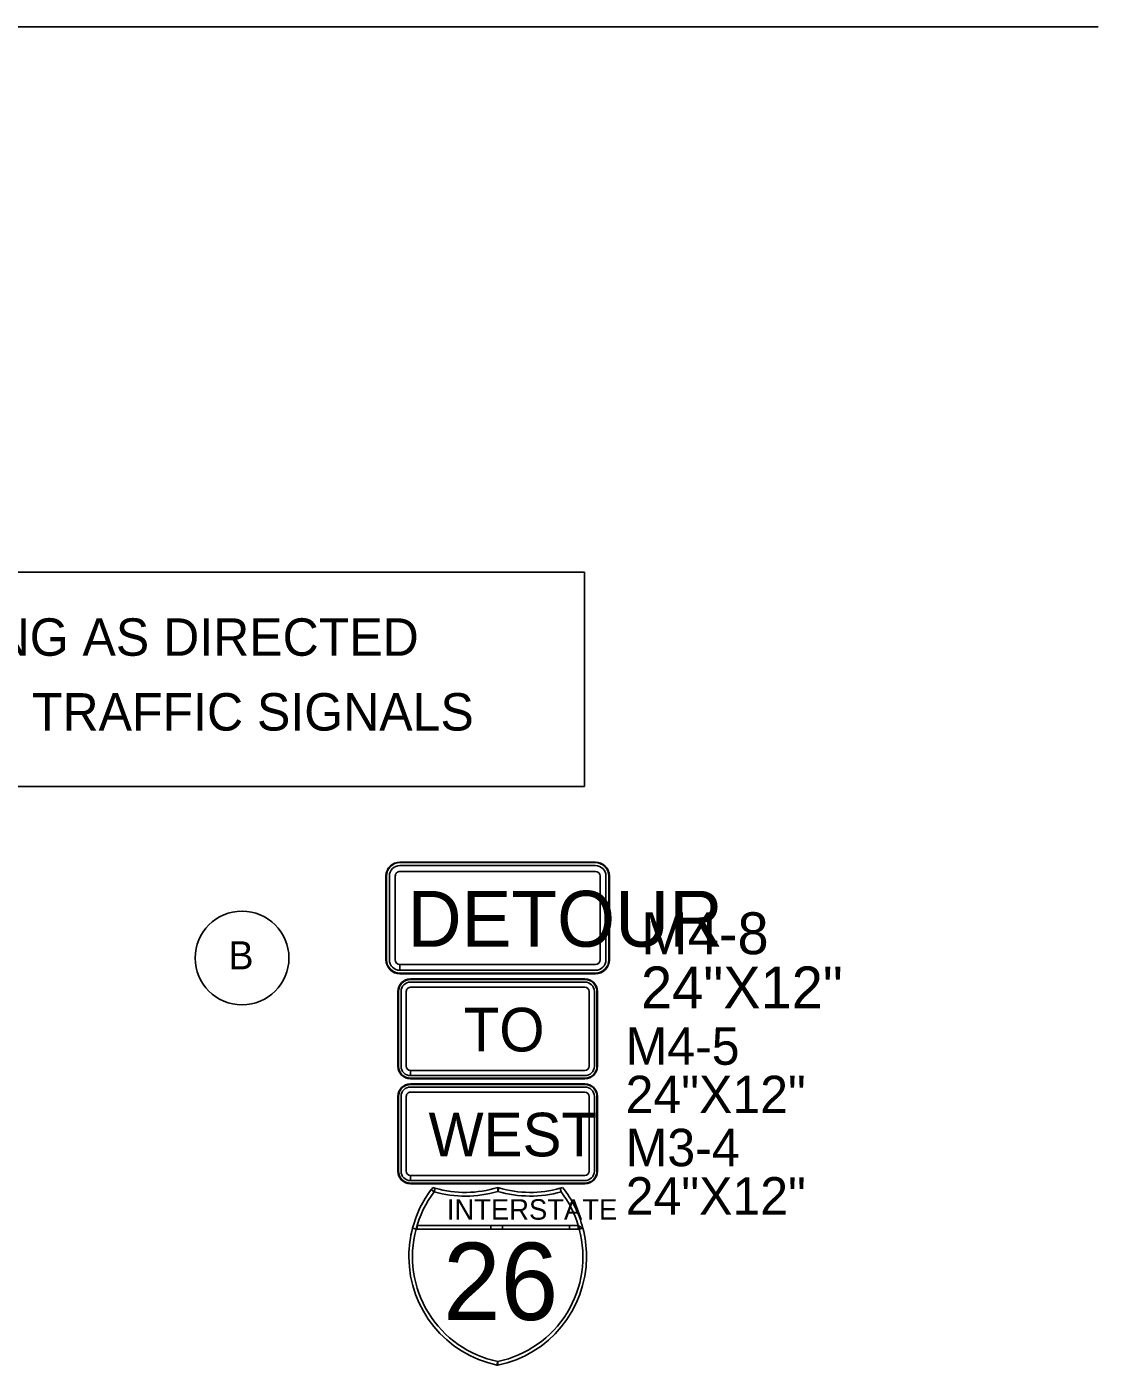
# Model space of a CAD drawing. Extents: x 886234 to 968767, y 455416 to 684046.
# Drawn here: x 935566 to 939863, y 530332 to 535699 of the extents above; entities that cross this region are included whole.
import ezdxf

# ---------------------------------------------------------------- set-up
doc = ezdxf.new("R2010")
doc.units = 0
for name, color, linetype in [('Scratch_Level_3', 7, 'Continuous'), ('TC DEV SIGN BLACK 239', 7, 'Continuous'), ('TC DEV SIGN BLACK ZERO', 7, 'Continuous'), ('TC DEV SIGN ORANGE', 7, 'Continuous'), ('TC DEV SIGN WHITE', 7, 'Continuous'), ('TC LABEL TEXT', 7, 'Continuous')]:
    doc.layers.add(name, color=color, linetype=linetype)

msp = doc.modelspace()

# ---------------------------------------------------------------- linework, layer by layer
at = {"layer": 'Scratch_Level_3'}
msp.add_line((904674.3, 535698.9), (939863.1, 535698.9), dxfattribs=at)
at = {"layer": 'TC DEV SIGN BLACK 239'}
for p, q in [((937067.2, 531409.7), (937067.2, 531109.7)), ((937088, 531409.7), (937088, 531109.7)), ((937804.8, 531447.2), (937104.7, 531447.2)), ((937804.8, 531426.4), (937104.7, 531426.4)), ((937821.4, 531109.7), (937821.4, 531409.7)), ((937842.3, 531109.7), (937842.3, 531409.7)), ((937104.7, 531072.2), (937104.7, 531093)), ((937104.9, 531093), (937804.8, 531093)), ((937104.9, 531093), (937104.9, 531072.2)), ((937104.9, 531072.2), (937804.8, 531072.2))]:
    msp.add_line(p, q, dxfattribs=at)
for centre, major_axis, start_param, end_param in [((937104.7, 531409.7), (37.5, 0), 1.570796, 3.141593), ((937104.7, 531409.7), (16.7, 0), 1.570796, 3.141593), ((937804.8, 531409.7), (37.5, 0), 0, 1.570796), ((937804.8, 531409.7), (16.7, 0), 0, 1.570796), ((937104.7, 531109.7), (37.5, 0), 3.141593, 4.712389), ((937104.7, 531109.7), (16.7, 0), 3.141593, 4.712389), ((937804.8, 531109.7), (37.5, 0), 4.712389, 6.283185), ((937804.8, 531109.7), (16.7, 0), 4.712389, 6.283185)]:
    msp.add_ellipse(centre, major_axis=major_axis, ratio=0.999865, start_param=start_param, end_param=end_param, dxfattribs=at)
at = {"layer": 'TC DEV SIGN BLACK ZERO'}
for p, q in [((937846.7, 532349.4), (937062.6, 532349.4)), ((937062.6, 532347), (937062.6, 532347.1)), ((937846.7, 532347), (937062.6, 532347.1)), ((937846.7, 532335.4), (937062.6, 532335.4)), ((937846.7, 532347), (937846.7, 532347)), ((937006.6, 532293.4), (937006.6, 531957.4)), ((937009, 532293.4), (937009, 531957.4)), ((937009, 532293.4), (937009, 532293.4)), ((937020.6, 532293.4), (937020.6, 531957.4)), ((937044, 532293.4), (937044, 531957.4)), ((937846.7, 532312), (937062.6, 532312)), ((937865.4, 531957.4), (937865.4, 532293.4)), ((937888.8, 531957.4), (937888.8, 532293.4)), ((937900.4, 532293.4), (937900.4, 532293.4)), ((937900.4, 531957.4), (937900.4, 532293.4)), ((937902.8, 531957.4), (937902.8, 532293.4)), ((937009, 531957.4), (937009, 531957.4)), ((937900.4, 531957.4), (937900.4, 531957.4)), ((937062.6, 531915.4), (937062.6, 531938.7)), ((937062.6, 531901.4), (937062.6, 531903.7)), ((937062.6, 531903.7), (937062.6, 531903.7)), ((937062.7, 531903.7), (937846.7, 531903.7)), ((937062.7, 531903.7), (937062.7, 531901.4)), ((937062.7, 531901.4), (937846.7, 531901.4)), ((937062.9, 531938.7), (937846.7, 531938.7)), ((937062.9, 531938.7), (937062.9, 531915.4)), ((937062.9, 531915.4), (937846.7, 531915.4)), ((937846.7, 531903.7), (937846.7, 531903.7)), ((937804.8, 531880.5), (937104.7, 531880.5)), ((937104.7, 531878.5), (937104.7, 531878.5)), ((937804.8, 531878.4), (937104.7, 531878.5)), ((937804.8, 531868), (937104.7, 531868)), ((937804.8, 531847.2), (937104.7, 531847.2)), ((937804.8, 531878.4), (937804.8, 531878.5)), ((937054.7, 531830.5), (937054.7, 531530.5)), ((937056.7, 531830.5), (937056.7, 531530.5)), ((937056.7, 531830.5), (937056.7, 531830.5)), ((937067.2, 531830.5), (937067.2, 531530.5)), ((937088, 531830.5), (937088, 531530.5)), ((937821.4, 531530.5), (937821.4, 531830.5)), ((937842.3, 531530.5), (937842.3, 531830.5)), ((937852.7, 531830.5), (937852.7, 531830.5)), ((937852.7, 531530.5), (937852.7, 531830.5)), ((937854.8, 531530.5), (937854.8, 531830.5)), ((937056.7, 531530.5), (937056.7, 531530.5)), ((937852.7, 531530.5), (937852.7, 531530.5)), ((937104.7, 531493), (937104.7, 531513.9)), ((937104.7, 531480.5), (937104.7, 531482.6)), ((937104.7, 531482.6), (937104.7, 531482.6)), ((937104.7, 531482.6), (937804.8, 531482.6)), ((937104.7, 531482.6), (937104.7, 531480.5)), ((937104.7, 531480.5), (937804.8, 531480.5)), ((937104.9, 531513.9), (937804.8, 531513.9)), ((937104.9, 531513.9), (937104.9, 531493)), ((937104.9, 531493), (937804.8, 531493)), ((937804.8, 531482.6), (937804.8, 531482.6)), ((937054.7, 531409.7), (937054.7, 531109.7)), ((937056.7, 531409.7), (937056.7, 531109.7)), ((937056.7, 531409.7), (937056.8, 531409.7)), ((937804.8, 531459.7), (937104.7, 531459.7)), ((937104.7, 531457.6), (937104.7, 531457.6)), ((937804.8, 531457.6), (937104.7, 531457.6)), ((937804.8, 531457.6), (937804.8, 531457.6)), ((937852.7, 531409.7), (937852.7, 531409.7)), ((937852.7, 531109.7), (937852.7, 531409.7)), ((937854.8, 531109.7), (937854.8, 531409.7)), ((937056.8, 531109.7), (937056.7, 531109.7)), ((937852.7, 531109.7), (937852.7, 531109.7)), ((937104.7, 531059.7), (937104.7, 531061.8)), ((937104.7, 531061.8), (937104.7, 531061.8)), ((937104.7, 531061.8), (937804.8, 531061.8)), ((937104.7, 531061.8), (937104.7, 531059.7)), ((937104.7, 531059.7), (937804.8, 531059.7)), ((937455.1, 531029.8), (937454.8, 531044.2)), ((937705.5, 531041.4), (937709.5, 531027.1)), ((937804.8, 531061.8), (937804.8, 531061.8)), ((937427.6, 530892.3), (937131.7, 530892.3)), ((937131.7, 530877.4), (937427.6, 530877.4)), ((937474.5, 530892.3), (937427.6, 530892.3)), ((937427.6, 530877.4), (937474.5, 530877.4)), ((937742.9, 530892.3), (937474.5, 530892.3)), ((937474.5, 530877.4), (937742.9, 530877.4)), ((937777.8, 530892.3), (937742.9, 530892.3)), ((937742.9, 530877.4), (937777.8, 530877.4)), ((937098.5, 530770.2), (937098.5, 530765.8)), ((937811, 530765.7), (937811, 530770.4))]:
    msp.add_line(p, q, dxfattribs=at)
for points in [[(937200, 531027.1), (937188.2, 531036.1)], [(937204.1, 531041.4), (937200, 531027.1)], [(937459.3, 531042.8), (937455.1, 531028.7)], [(937709.5, 531027.1), (937705.5, 531041.4)], [(937715, 531044.2), (937715, 531044.2), (937715, 531044.2)], [(937454.8, 531028.7), (937455.1, 531029.8)], [(937127.5, 530877.4), (937113.1, 530881.2)], [(937113.1, 530881.2), (937127.5, 530877.4)], [(937131.7, 530892.3), (937131.7, 530877.4)], [(937427.6, 530892.3), (937427.6, 530877.4)], [(937427.6, 530877.4), (937427.6, 530892.3)], [(937474.5, 530892.3), (937474.5, 530877.4)], [(937474.5, 530877.4), (937474.5, 530892.3)], [(937742.9, 530892.3), (937742.9, 530877.4)], [(937742.9, 530877.4), (937742.9, 530892.3)], [(937777.8, 530892.3), (937796.4, 530881.2)], [(937777.8, 530877.4), (937777.8, 530892.3)], [(937796.4, 530881.2), (937782, 530877.4)], [(937451.7, 530332.3), (937454.8, 530346.9)], [(937454.8, 530346.9), (937454.8, 530331.7)]]:
    msp.add_lwpolyline(points, dxfattribs=at)
for centre, radius, start, end in [((937543.8, 530768), 445.3, 142.9968, 165.2769), ((937324.6, 531470.1), 445.3, 254.2907, 286.9893), ((937584.9, 531470.1), 445.3, 253.6206, 285.7093), ((937584.9, 531470.1), 445.3, 285.7093, 286.9901), ((937365.7, 530768), 445.3, 14.7231, 38.3291), ((937543.8, 530768), 430.5, 142.9968, 165.2769), ((937324.6, 531470.1), 460.2, 254.2907, 286.4259), ((937585.1, 531469.4), 459.4, 253.5731, 285.7093), ((937365.7, 530768), 430.5, 16.7759, 37.0032), ((937543.8, 530768), 445.3, 165.2769, 179.7177), ((937541.7, 530766.7), 428.8, 165.0438, 258.3001), ((937367.8, 530766.7), 428.8, 281.7196, 14.964), ((937365.7, 530768), 445.3, 0.2997, 14.7231), ((937543.8, 530768), 445.3, 180.2823, 258.0591), ((937365.7, 530768), 445.3, 281.537, 359.7003), ((937365.7, 530768), 430.5, 281.9405, 281.9604)]:
    msp.add_arc(centre, radius, start, end, dxfattribs=at)
for centre, major_axis, start_param, end_param in [((937062.6, 532293.4), (56, 0), 1.570796, 3.141593), ((937062.6, 532293.4), (53.7, 0), 1.570796, 3.141593), ((937062.6, 532293.4), (42, 0), 1.570796, 3.141593), ((937846.7, 532293.4), (56, 0), 0, 1.570796), ((937846.7, 532293.4), (53.7, 0), 0, 1.570796), ((937846.7, 532293.4), (42, 0), 0, 1.570796), ((937062.6, 532293.4), (18.7, 0), 1.570796, 3.141593), ((937846.7, 532293.4), (18.7, 0), 0, 1.570796), ((937062.6, 531957.4), (56, 0), 3.141593, 4.712389), ((937062.6, 531957.4), (53.7, 0), 3.141593, 4.712389), ((937062.6, 531957.4), (42, 0), 3.141593, 4.712389), ((937062.6, 531957.4), (18.7, 0), 3.141593, 4.712389), ((937846.7, 531957.4), (42, 0), 4.712389, 6.283185), ((937846.7, 531957.4), (18.7, 0), 4.712389, 6.283185), ((937846.7, 531957.4), (56, 0), 4.712389, 6.283185), ((937846.7, 531957.4), (53.7, 0), 4.712389, 6.283185), ((937104.7, 531830.5), (50, 0), 1.570796, 3.141593), ((937104.7, 531830.5), (47.9, 0), 1.570796, 3.141593), ((937104.7, 531830.5), (37.5, 0), 1.570796, 3.141593), ((937104.7, 531830.5), (16.7, 0), 1.570796, 3.141593), ((937804.8, 531830.5), (50, 0), 0, 1.570796), ((937804.8, 531830.5), (47.9, 0), 0, 1.570796), ((937804.8, 531830.5), (37.5, 0), 0, 1.570796), ((937804.8, 531830.5), (16.7, 0), 0, 1.570796), ((937104.7, 531530.5), (50, 0), 3.141593, 4.712389), ((937104.7, 531530.5), (47.9, 0), 3.141593, 4.712389), ((937104.7, 531530.5), (37.5, 0), 3.141593, 4.712389), ((937104.7, 531530.5), (16.7, 0), 3.141593, 4.712389), ((937804.8, 531530.5), (37.5, 0), 4.712389, 6.283185), ((937804.8, 531530.5), (16.7, 0), 4.712389, 6.283185), ((937804.8, 531530.5), (50, 0), 4.712389, 6.283185), ((937804.8, 531530.5), (47.9, 0), 4.712389, 6.283185), ((937104.7, 531409.7), (50, 0), 1.570796, 3.141593), ((937104.7, 531409.7), (47.9, 0), 1.570796, 3.141593), ((937804.8, 531409.7), (50, 0), 0, 1.570796), ((937804.8, 531409.7), (47.9, 0), 0, 1.570796), ((937104.7, 531109.7), (50, 0), 3.141593, 4.712389), ((937104.7, 531109.7), (47.9, 0), 3.141593, 4.712389), ((937804.8, 531109.7), (50, 0), 4.712389, 6.283185), ((937804.8, 531109.7), (47.9, 0), 4.712389, 6.283185)]:
    msp.add_ellipse(centre, major_axis=major_axis, ratio=0.999865, start_param=start_param, end_param=end_param, dxfattribs=at)
at = {"layer": 'TC DEV SIGN ORANGE'}
for p, q in [((937846.7, 532349.4), (937062.6, 532349.4)), ((937006.6, 532293.4), (937006.6, 531957.4)), ((937902.8, 531957.4), (937902.8, 532293.4)), ((937062.6, 531901.4), (937846.7, 531901.4)), ((937804.8, 531880.5), (937104.7, 531880.5)), ((937054.7, 531830.5), (937054.7, 531530.5)), ((937854.8, 531530.5), (937854.8, 531830.5)), ((937104.7, 531480.5), (937804.8, 531480.5))]:
    msp.add_line(p, q, dxfattribs=at)
for centre, major_axis, start_param, end_param in [((937062.6, 532293.4), (56, 0), 1.570796, 3.141593), ((937846.7, 532293.4), (56, 0), 0, 1.570796), ((937062.6, 531957.4), (56, 0), 3.141593, 4.712389), ((937846.7, 531957.4), (56, 0), 4.712389, 6.283185), ((937104.7, 531830.5), (50, 0), 1.570796, 3.141593), ((937804.8, 531830.5), (50, 0), 0, 1.570796), ((937104.7, 531530.5), (50, 0), 3.141593, 4.712389), ((937804.8, 531530.5), (50, 0), 4.712389, 6.283185)]:
    msp.add_ellipse(centre, major_axis=major_axis, ratio=0.999865, start_param=start_param, end_param=end_param, dxfattribs=at)
at = {"layer": 'TC DEV SIGN WHITE'}
for p, q in [((937054.7, 531409.7), (937054.7, 531109.7)), ((937804.8, 531459.7), (937104.7, 531459.7)), ((937854.8, 531109.7), (937854.8, 531409.7)), ((937104.7, 531059.7), (937804.8, 531059.7)), ((937200, 531027.1), (937204.1, 531041.4)), ((937455.1, 531028.7), (937454.8, 531044.2)), ((937127.5, 530877.4), (937782, 530877.4)), ((937127.5, 530877.4), (937131.7, 530877.4)), ((937131.7, 530892.3), (937777.8, 530892.3)), ((937796.4, 530881.2), (937777.8, 530892.3)), ((937781.7, 530878.5), (937777.8, 530877.4)), ((937777.8, 530877.4), (937782, 530877.4)), ((937454.8, 530331.7), (937454.8, 530346.9))]:
    msp.add_line(p, q, dxfattribs=at)
for points in [[(937188.2, 531036.1), (937200, 531027.1)], [(937194.5, 531044.2), (937194.5, 531044.2), (937194.5, 531044.2)], [(937455.1, 531044.1), (937455.1, 531029.8), (937459.3, 531042.8)], [(937131.7, 530877.4), (937131.7, 530892.3)], [(937777.8, 530892.3), (937777.8, 530877.4), (937781.7, 530878.5), (937777.8, 530892.3)], [(937782, 530877.4), (937781.7, 530878.5)], [(937782, 530877.4), (937796.4, 530881.2)], [(937454.8, 530346.9), (937451.7, 530332.3), (937454.7, 530331.7)]]:
    msp.add_lwpolyline(points, dxfattribs=at)
for centre, radius, start, end in [((937543.8, 530768), 445.3, 141.6709, 142.9968), ((937324.6, 531470.1), 445.3, 253.0099, 254.2907), ((937584.9, 531470.1), 445.3, 253.0588, 253.6206), ((937543.8, 530768), 430.5, 163.2241, 165.2769), ((937365.7, 530768), 430.5, 14.7231, 16.7759), ((937543.8, 530768), 445.3, 258.458, 258.463), ((937365.7, 530768), 445.3, 281.5369590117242, 281.53700435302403)]:
    msp.add_arc(centre, radius, start, end, dxfattribs=at)
for centre, start_param, end_param in [((937104.7, 531409.7), 1.570796, 3.141593), ((937804.8, 531409.7), 0, 1.570796), ((937104.7, 531109.7), 3.141593, 4.712389), ((937804.8, 531109.7), 4.712389, 6.283185)]:
    msp.add_ellipse(centre, major_axis=(50, 0), ratio=0.999865, start_param=start_param, end_param=end_param, dxfattribs=at)
at = {"layer": 'TC LABEL TEXT'}
msp.add_lwpolyline([(932106.9, 533511.7), (937802.2, 533511.7), (937802.2, 532652.5), (932106.9, 532652.5)], close=True, dxfattribs=at)
msp.add_circle((936429.3, 531964.7), 188.1, dxfattribs=at)

# ---------------------------------------------------------------- texts
at = {"layer": 'TC DEV SIGN BLACK 239'}
msp.add_text('WEST', height=175, rotation=360, dxfattribs=at).set_placement((937177.4, 531169.2))
at = {"layer": 'TC DEV SIGN BLACK ZERO'}
msp.add_text('DETOUR', height=224, dxfattribs=at).set_placement((937093.7, 532010))
for s, height, p in [('M4-8', 168, (938029.5, 531979.9)), ('24"X12"', 168, (938029.5, 531762.6)), ('TO', 175, (937317.9, 531590)), ('M4-5', 150, (937967.7, 531536.5)), ('24"X12"', 150, (937967.7, 531342.5)), ('M3-4', 150, (937968, 531129.8)), ('24"X12"', 150, (937968, 530935.8)), ('INTERSTATE', 82.13, (937250.7, 530915.3)), ('26', 310.26, (937235.8, 530513))]:
    msp.add_text(s, height=height, rotation=360, dxfattribs=at).set_placement(p)
at = {"layer": 'TC LABEL TEXT'}
for s, height, p in [('ADJUST EXISTING SIGNAL TIMING AS DIRECTED', 150, (932412.7, 533176.7)), ('BY THE ENGINEER AT IMPACTED TRAFFIC SIGNALS', 150, (932299, 532876.7)), ('B', 112.5, (936375.2, 531919.3))]:
    msp.add_text(s, height=height, dxfattribs=at).set_placement(p)

doc.saveas('drawing.dxf')
